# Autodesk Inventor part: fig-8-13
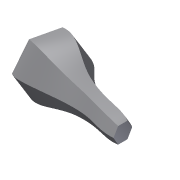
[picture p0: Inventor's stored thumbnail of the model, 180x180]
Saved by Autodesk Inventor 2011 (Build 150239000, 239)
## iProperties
Created: 2004-05
Part Number: fig-8-13
Document SubType Name: Modeling
Designer: CADCIM Technologies
Manufacturer: Standard
Standards Organization: Custom
Density: 1 g/cm^3
Author: CADCIM Technologies
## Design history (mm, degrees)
workplane "Work Plane2"
sketch "Sketch7"
  geometry: L1 (-42.583, 6.068)-(-42.583, 0.37) reference; 5 further points
  constraints: 1 point on line, 5 other
sketch "Sketch8"
  geometry: L1 (-42.583, 3.219)-(-107.269, 18.236); L2 (-42.583, 6.068)-(-42.583, 0.37) reference
  constraints: 2 end point, 1 midpoint
sweep "Sweep7" sketch "Sketch7", "Sketch8" dims "d6" = 0
body "Solid1"
sketch "Sketch2"
  geometry: L1 (-5.697, 0)-(-2.849, 4.934); L2 (-2.849, 4.934)-(2.849, 4.934); L3 (2.849, 4.934)-(5.697, 0); L4 (5.697, 0)-(2.849, -4.934); L5 (2.849, -4.934)-(-2.849, -4.934); L6 (-2.849, -4.934)-(-5.697, 0); 2 further points
  constraints: 12 end point, 1 coincident, 12 other
